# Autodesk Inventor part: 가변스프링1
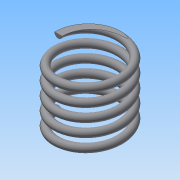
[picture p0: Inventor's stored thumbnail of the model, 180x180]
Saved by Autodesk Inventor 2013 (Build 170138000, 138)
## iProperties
Created: 2016-03
Part Number: 가변스프링1
Material: Generic
Document SubType Name: Modeling
Designer: Administrator
Density: 1 g/cm^3
Mass: 0.823417 g
Surface Area: 16.7135 cm^2
Volume: 0.823417 cm^3
Author: Administrator
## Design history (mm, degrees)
sketch "스케치1"
  geometry: L1 (0, 0)-(8.5, 0); L2 (8.5, 17.5)-(0, 17.5); L3 (0, 17.5)-(0, 0); C1 r 1 at (8.5, 0)
  constraints: 6 end point, 2 parallel, 1 centre point, 1 coincident, 1 horizontal, 1 vertical
  dimensions: "d0" = 2 diameter of C1; "d1" = 17 diameter of C1.centre L3; "d2" = 17.5 distance between parallel lines of L1 L2 (derived)
feature "코일1" sketch "스케치1" pitch "d3" = 10; turns "d5" = 5; dims "d4" = 17.5 (= d2), "d6" = 0, angle "d7" = 90 deg, angle "d8" = 90 deg, "d9" = 0, "d10" = 0
sketch "스케치2"
  geometry: L1 (-10, 17.5)-(10, 17.5); L2 (10, 17.5)-(10, 0); L3 (10, 0)-(-10, 0); L4 (-10, 0)-(-10, 17.5); 2 further points
  constraints: 8 end point, 2 parallel, 1 coincident, 1 horizontal, 1 midpoint, 1 perpendicular
  dimensions: "d11" = 17.5 distance between parallel lines of L3 L1 (derived); "d13" = 20 distance of L1.start L1.end
extrude "돌출1" sketch "스케치2" stored distance "d14" = 10; taper "d15" = 0 deg
node "솔리드1"
